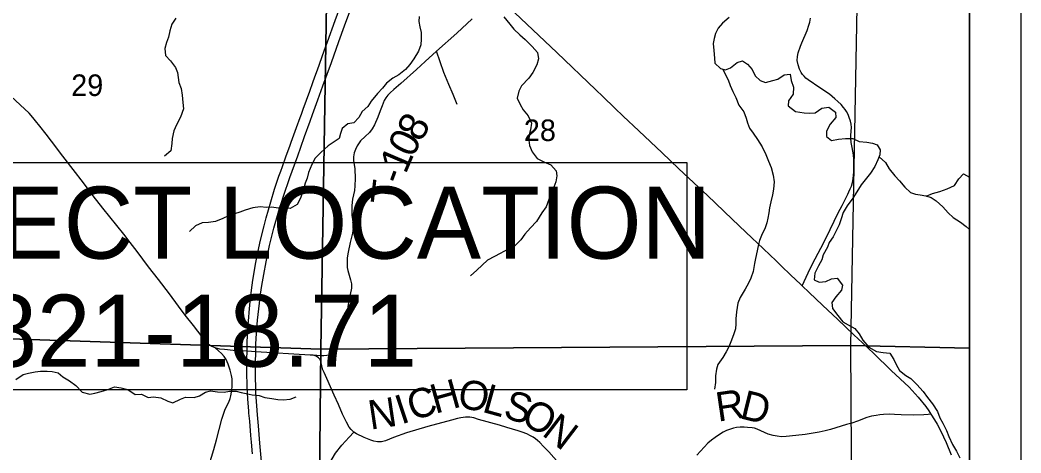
# Model space of a CAD drawing. Extents: x 0 to 34, y 0 to 22.
# Drawn here: x 28.471 to 30.417, y 15.384 to 16.225 of the extents above; entities that cross this region are included whole.
import ezdxf

# ---------------------------------------------------------------- set-up
doc = ezdxf.new("R2010")
doc.units = 0
for name, color, linetype in [('GM_X_Corporation', 7, 'Continuous'), ('GM_X_County_Road', 7, 'Continuous'), ('GM_X_County_Road_Text', 7, 'Continuous'), ('GM_X_Interstate_Route', 7, 'Continuous'), ('GM_X_Minor_River', 7, 'Continuous'), ('GM_X_Section_Text', 7, 'Continuous'), ('GM_X_State_Route', 7, 'Continuous'), ('GM_X_Township_Road', 7, 'Continuous'), ('GM_X_Township_Road_Text', 7, 'Continuous'), ('SH_Data', 7, 'Continuous'), ('SH_Masking', 7, 'Continuous'), ('SH_Text', 7, 'Continuous')]:
    doc.layers.add(name, color=color, linetype=linetype)

msp = doc.modelspace()

# ---------------------------------------------------------------- linework, layer by layer
at = {"layer": 'GM_X_Corporation'}
for points in [[(23.5167, 14.1), (30.3167, 14.1), (30.3167, 18.565), (30.101, 18.5701), (29.6772, 18.5786), (29.6561, 18.5791), (29.0074, 18.5935), (28.7772, 18.6028), (28.3421, 18.6121), (27.3971, 18.6436), (27.1064, 18.6537), (27.1039, 18.5696), (27.0944, 18.0731), (27.0775, 16.888), (27.0694, 16.6556), (27.0676, 16.5549), (27.052, 15.403), (27.043, 14.755), (27.046, 14.6155), (27.01, 14.6164), (26.6535, 14.621)], [(27.0676, 16.5549), (27.052, 15.403), (27.043, 14.755), (27.046, 14.6155), (27.2076, 14.6118), (27.2151, 14.6117), (27.2601, 14.6106), (27.262, 14.6106), (27.3217, 14.6092), (27.3244, 14.6092), (28.7538, 14.5726), (28.7592, 14.5724), (28.9743, 14.568), (28.9779, 14.5679), (28.9904, 14.5676), (29.257, 14.5621), (29.2606, 14.562), (30.0913, 14.5411), (30.0947, 14.5411), (30.3167, 14.5373), (30.3167, 18.565)]]:
    msp.add_lwpolyline(points, dxfattribs=at)
for points in [[(28.0831, 16.631), (29.0727, 16.6129), (29.0554, 15.5858), (28.0603, 15.6194)], [(29.0727, 16.6129), (30.104, 16.5971), (30.0852, 15.5935), (29.0554, 15.5858)], [(30.3167, 15.5879), (30.3167, 16.5929), (30.104, 16.5971), (30.0852, 15.5935)], [(29.0554, 15.5858), (29.0455, 14.5648), (28.107, 14.591), (28.0653, 14.5914), (28.0603, 15.6194)], [(30.0852, 15.5935), (30.0916, 14.542), (29.1115, 14.5644), (29.0455, 14.5648), (29.0554, 15.5858)], [(30.3167, 14.5377), (30.3167, 15.5879), (30.0852, 15.5935), (30.0916, 14.542)]]:
    msp.add_lwpolyline(points, close=True, dxfattribs=at)
at = {"layer": 'GM_X_County_Road'}
for points in [[(29.0586, 15.5484), (29.0574, 15.5535), (29.056, 15.5595), (29.0548, 15.5639), (29.0534, 15.5665), (29.051, 15.5691), (29.0467, 15.5722), (29.0404, 15.5742), (29.0348, 15.5747), (28.929, 15.581), (28.9122, 15.5822), (28.8854, 15.5838), (28.8681, 15.5851), (28.8594, 15.5862), (28.85, 15.5884), (28.8438, 15.5911), (28.8375, 15.5954), (28.8311, 15.6014), (28.8247, 15.6099), (28.8081, 15.6319), (28.7917, 15.6523), (28.7789, 15.6696), (28.7617, 15.6935), (28.7403, 15.7211), (28.7208, 15.7459), (28.6986, 15.7755), (28.6848, 15.7933), (28.6725, 15.8093), (28.632, 15.8603), (28.6131, 15.8842), (28.5945, 15.909), (28.5542, 15.9607), (28.5319, 15.9899), (28.5215, 16.0038), (28.5095, 16.0195), (28.5012, 16.0297), (28.496, 16.036), (28.4885, 16.0443), (28.4445, 16.0856)], [(28.8362, 15.3529), (28.8476, 15.3911), (28.8529, 15.4102), (28.8634, 15.4499), (28.8699, 15.4692), (28.8768, 15.4828), (28.8796, 15.4905), (28.8807, 15.4951), (28.8819, 15.5024), (28.8832, 15.5132), (28.8835, 15.5205), (28.8835, 15.5283), (28.8821, 15.5352), (28.8794, 15.5451), (28.8753, 15.5568), (28.8716, 15.5657), (28.8678, 15.5719), (28.8622, 15.5778), (28.8564, 15.5829), (28.85, 15.5884)], [(29.5282, 15.3538), (29.4987, 15.3865), (29.4886, 15.3972), (29.4816, 15.4049), (29.4771, 15.4089), (29.4728, 15.4121), (29.4682, 15.4154), (29.4632, 15.418), (29.456, 15.4214), (29.4472, 15.4248), (29.4391, 15.4274), (29.4174, 15.4342), (29.4028, 15.4386), (29.3619, 15.4496), (29.3529, 15.4524), (29.3453, 15.4538), (29.3367, 15.4541), (29.328, 15.4528), (29.3214, 15.4514), (29.3094, 15.4484), (29.2637, 15.4356), (29.2219, 15.4234), (29.1969, 15.4142), (29.1812, 15.4079), (29.1736, 15.4059), (29.1659, 15.4058), (29.1585, 15.4074), (29.1527, 15.4092), (29.1398, 15.4146), (29.125, 15.4213), (29.1195, 15.425), (29.1145, 15.4297), (29.1107, 15.4348), (29.1056, 15.4442), (29.098, 15.4601), (29.0902, 15.4783), (29.0817, 15.4969), (29.0674, 15.529), (29.0619, 15.541), (29.0588, 15.5473), (29.0586, 15.5484)], [(30.2417, 15.4597), (30.2362, 15.4589), (30.228, 15.4585), (30.2084, 15.4581), (30.184, 15.4588), (30.171, 15.4591), (30.161, 15.4595), (30.1497, 15.4593), (30.1422, 15.4585), (30.1349, 15.4574), (30.1259, 15.4556), (30.1173, 15.4531), (30.0987, 15.4463), (30.0877, 15.4426), (30.0772, 15.4397), (30.0464, 15.4303), (30.0357, 15.4276), (30.0242, 15.4249), (29.9971, 15.4202), (29.9912, 15.4195), (29.9599, 15.4161), (29.9508, 15.416), (29.9429, 15.4169), (29.9349, 15.4184), (29.9255, 15.4212), (29.9037, 15.4307), (29.8987, 15.4323), (29.8938, 15.4331), (29.8853, 15.4341), (29.8783, 15.4344), (29.8706, 15.4343), (29.8636, 15.4337), (29.8579, 15.4325), (29.8503, 15.4302), (29.8444, 15.4279), (29.8375, 15.4247), (29.8304, 15.4204), (29.8219, 15.4146), (29.815, 15.4094), (29.8077, 15.4032), (29.7862, 15.3803)]]:
    msp.add_lwpolyline(points, dxfattribs=at)
at = {"layer": 'GM_X_Interstate_Route'}
for points in [[(28.9229, 15.3828), (28.921, 15.4055), (28.9197, 15.4182), (28.9173, 15.4465), (28.9159, 15.4616), (28.9155, 15.4664), (28.9139, 15.4887), (28.9125, 15.5152), (28.9117, 15.5401), (28.9117, 15.56), (28.9118, 15.5674), (28.9122, 15.5822), (28.9124, 15.5998), (28.9131, 15.612), (28.9138, 15.6267), (28.9153, 15.648), (28.9162, 15.6572), (28.9191, 15.6855), (28.9236, 15.72), (28.9295, 15.7547), (28.9333, 15.7736), (28.9384, 15.7981), (28.9451, 15.8255), (28.949, 15.841), (28.9581, 15.8722), (28.9655, 15.8969), (28.9741, 15.9224), (28.9776, 15.9319), (28.9808, 15.9411), (28.9883, 15.9619), (28.9951, 15.9805), (28.9976, 15.9881), (29.0082, 16.0169), (29.0153, 16.036), (29.0177, 16.0426), (29.021, 16.0522), (29.034, 16.0873), (29.0402, 16.1044), (29.044, 16.1151), (29.0489, 16.1286), (29.0621, 16.1659), (29.0684, 16.1829), (29.0835, 16.2246), (29.0946, 16.2545)], [(28.9414, 15.3536), (28.9371, 15.4037), (28.9341, 15.4369), (28.9324, 15.4585), (28.9293, 15.5021), (28.9292, 15.5108), (28.9285, 15.5325), (28.9285, 15.5596), (28.929, 15.581), (28.9295, 15.5962), (28.9305, 15.6163), (28.9326, 15.6424), (28.9361, 15.6752), (28.9383, 15.6931), (28.9408, 15.71), (28.9445, 15.7308), (28.9491, 15.7557), (28.9561, 15.7875), (28.9597, 15.8032), (28.9642, 15.8209), (28.9739, 15.8551), (28.9828, 15.8832), (28.9952, 15.9196), (29.0107, 15.9619), (29.0169, 15.9787), (29.024, 15.9989), (29.0351, 16.0292), (29.0395, 16.0421), (29.0497, 16.0705), (29.0596, 16.0974), (29.0763, 16.1429), (29.0907, 16.184), (29.1019, 16.2142), (29.1175, 16.2573)]]:
    msp.add_lwpolyline(points, dxfattribs=at)
at = {"layer": 'GM_X_Minor_River'}
for points in [[(28.7736, 16.2294), (28.7657, 16.2177), (28.7623, 16.2044), (28.7594, 16.1919), (28.7556, 16.182), (28.7522, 16.1702), (28.7534, 16.1566), (28.7633, 16.1464), (28.7728, 16.1332), (28.777, 16.1233), (28.7793, 16.1044), (28.7839, 16.0926), (28.7862, 16.0794), (28.787, 16.065), (28.7885, 16.0529), (28.7829, 16.0369), (28.775, 16.0217), (28.7697, 16.01), (28.7667, 15.9955), (28.766, 15.9857), (28.7638, 15.9713), (28.7517, 15.961)], [(29.2465, 16.2322), (29.2462, 16.2224), (29.2481, 16.2125), (29.2504, 16.2015), (29.2508, 16.1886), (29.2497, 16.1776), (29.2452, 16.1647), (29.2362, 16.1503), (29.2283, 16.1389), (29.2199, 16.1294), (29.2071, 16.1191), (29.1958, 16.1123), (29.1833, 16.1027), (29.1754, 16.0932), (29.1659, 16.083), (29.1535, 16.0681), (29.1467, 16.0575), (29.1361, 16.0476), (29.1294, 16.0358), (29.1195, 16.026), (29.1078, 16.024), (29.0972, 16.0145), (29.0939, 16.005), (29.0909, 15.9951), (29.0795, 15.9875), (29.0697, 15.981), (29.0553, 15.9681), (29.0448, 15.9571), (29.038, 15.9445), (29.0316, 15.929), (29.029, 15.9184), (29.0252, 15.9085), (29.0215, 15.8945), (29.0162, 15.8793), (29.0094, 15.8671), (28.9958, 15.8595), (28.9826, 15.8602), (28.9727, 15.8602), (28.9606, 15.862), (28.95, 15.8612), (28.9379, 15.8623), (28.9235, 15.8604), (28.9088, 15.8558), (28.8978, 15.8523), (28.888, 15.8489), (28.8759, 15.8454), (28.8653, 15.8401), (28.8505, 15.8343), (28.8373, 15.832), (28.8252, 15.8312), (28.8119, 15.8255), (28.8002, 15.8145)], [(29.4112, 16.2316), (29.423, 16.2177), (29.431, 16.2078), (29.4424, 16.1965), (29.4526, 16.1878), (29.4663, 16.1738), (29.4766, 16.1621), (29.4789, 16.15), (29.4755, 16.1382), (29.4676, 16.1234), (29.4601, 16.1128), (29.4457, 16.0976), (29.4404, 16.0873), (29.4371, 16.0737), (29.4428, 16.0616), (29.4489, 16.0513), (29.4584, 16.0392), (29.4649, 16.0252), (29.463, 16.0123), (29.4608, 16.0025), (29.46, 15.9922), (29.4612, 15.9816), (29.4665, 15.9691), (29.4764, 15.9563), (29.4893, 15.9499), (29.5026, 15.9439), (29.5132, 15.9325), (29.5144, 15.9231), (29.5125, 15.9113), (29.5088, 15.9007), (29.5027, 15.8878), (29.499, 15.8771), (29.4934, 15.8623), (29.4854, 15.8506), (29.4749, 15.8342), (29.4632, 15.8221), (29.4522, 15.8095), (29.4443, 15.7985), (29.4322, 15.7859), (29.4186, 15.7798), (29.4043, 15.7718), (29.3929, 15.7661), (29.3797, 15.7592), (29.3691, 15.749), (29.3589, 15.7398), (29.3465, 15.7288)], [(29.8493, 16.2301), (29.8365, 16.2191), (29.8278, 16.2096), (29.8229, 16.1993), (29.8199, 16.1898), (29.818, 16.18), (29.8196, 16.166), (29.8208, 16.1516), (29.8216, 16.1417), (29.8326, 16.1315), (29.842, 16.1289), (29.8519, 16.1327), (29.8647, 16.143), (29.8753, 16.1461), (29.8852, 16.14), (29.8939, 16.1291), (29.8996, 16.1173), (29.9095, 16.1083), (29.9201, 16.1041), (29.9341, 16.1083), (29.944, 16.1103), (29.9564, 16.119), (29.9678, 16.1206), (29.9701, 16.1081), (29.9747, 16.0948), (29.9736, 16.0816), (29.9649, 16.0687), (29.9642, 16.0588), (29.9786, 16.0479), (29.9949, 16.0449), (30.0055, 16.0445), (30.0165, 16.0453), (30.0293, 16.0545), (30.0433, 16.0564), (30.0558, 16.0466), (30.0566, 16.0364), (30.0457, 16.0231), (30.0385, 16.0098), (30.0389, 15.9992), (30.0484, 15.9916), (30.0621, 15.9943), (30.0753, 15.9955)], [(29.8363, 16.1305), (29.8474, 16.1096), (29.8516, 16.0986), (29.8566, 16.0865), (29.8623, 16.0747), (29.868, 16.06), (29.8779, 16.0471), (29.8825, 16.035), (29.8848, 16.0255), (29.8886, 16.0153), (29.8958, 16.0055), (29.9042, 15.9934), (29.9133, 15.9794), (29.9205, 15.9643), (29.9259, 15.9514), (29.9312, 15.9393), (29.9347, 15.9241), (29.9366, 15.9112), (29.9355, 15.8972), (29.9336, 15.8858), (29.9306, 15.8722), (29.9277, 15.8604), (29.9265, 15.8509), (29.9247, 15.8407), (29.9224, 15.8312), (29.9187, 15.8198), (29.9134, 15.81), (29.9085, 15.7974), (29.9055, 15.7868), (29.9037, 15.7773), (29.9003, 15.7622), (29.8984, 15.7527), (29.8958, 15.7371), (29.8917, 15.7242), (29.8872, 15.7143), (29.8804, 15.7026), (29.8706, 15.6862), (29.8665, 15.6756), (29.8635, 15.6589), (29.8624, 15.6453), (29.8624, 15.6354), (29.8617, 15.6256), (29.8587, 15.6161), (29.8538, 15.6035), (29.8489, 15.5906), (29.8433, 15.5808), (29.8373, 15.5698), (29.8275, 15.5565), (29.8245, 15.547), (29.823, 15.5341), (29.8226, 15.5216), (29.8208, 15.5083)], [(30.0753, 15.9955), (30.0897, 15.9952), (30.1022, 15.9895), (30.117, 15.9884), (30.128, 15.9862), (30.1374, 15.9832), (30.1428, 15.973), (30.1424, 15.9635), (30.1387, 15.954), (30.1323, 15.9411), (30.124, 15.9278), (30.1164, 15.9183), (30.1062, 15.905), (30.0976, 15.8917), (30.09, 15.8796), (30.0787, 15.8647), (30.0708, 15.8514), (30.0674, 15.8393), (30.0633, 15.8279), (30.0573, 15.8158), (30.0513, 15.804), (30.0441, 15.7933), (30.0403, 15.7839), (30.0324, 15.7694), (30.0294, 15.7599), (30.023, 15.7478), (30.0159, 15.7337), (30.0148, 15.7208), (30.0243, 15.716), (30.0371, 15.7175), (30.0485, 15.7225), (30.0594, 15.7237), (30.0697, 15.7104), (30.0678, 15.7006), (30.0565, 15.688), (30.049, 15.6766), (30.0505, 15.6652), (30.0608, 15.6513), (30.0703, 15.6392), (30.0809, 15.6331), (30.0934, 15.6264), (30.1018, 15.6161), (30.109, 15.6037), (30.1208, 15.5901), (30.1356, 15.5814), (30.1488, 15.5795), (30.1617, 15.5781), (30.1697, 15.566), (30.1739, 15.5561), (30.1804, 15.5448), (30.1925, 15.5346), (30.2028, 15.5289), (30.2145, 15.5176), (30.2263, 15.5036), (30.2351, 15.4919), (30.2449, 15.4798), (30.2544, 15.465), (30.259, 15.4526), (30.2647, 15.4423), (30.2716, 15.428), (30.2766, 15.4162), (30.2838, 15.4011), (30.291, 15.3882), (30.2975, 15.375)], [(30.1409, 15.9598), (30.1531, 15.9484), (30.1607, 15.9363), (30.1717, 15.923), (30.1804, 15.9132), (30.1907, 15.9011), (30.2017, 15.8905), (30.2116, 15.8875), (30.221, 15.8857), (30.2316, 15.8838), (30.2419, 15.8804), (30.2521, 15.874), (30.2646, 15.8627), (30.2753, 15.8506), (30.2851, 15.8416), (30.2988, 15.8325), (30.3098, 15.8246), (30.3167, 15.8188)], [(30.2325, 15.8835), (30.2449, 15.8888), (30.2592, 15.8923), (30.2732, 15.8976), (30.2876, 15.9037), (30.2959, 15.917), (30.3046, 15.9265), (30.3167, 15.9205)], [(28.4626, 15.5271), (28.4769, 15.537), (28.4875, 15.5397), (28.5, 15.542), (28.5106, 15.5435), (28.5235, 15.5432), (28.5333, 15.5425), (28.5447, 15.5399), (28.5542, 15.5323), (28.5667, 15.5244), (28.5796, 15.5157), (28.5914, 15.5025), (28.6062, 15.4984), (28.6164, 15.5003), (28.6285, 15.5038), (28.6417, 15.508), (28.6546, 15.5126), (28.6675, 15.5111), (28.6807, 15.5077), (28.6944, 15.4979), (28.7069, 15.4984), (28.7201, 15.4923), (28.7304, 15.4935), (28.7448, 15.4913), (28.7584, 15.4849), (28.7679, 15.4819), (28.783, 15.4892), (28.7928, 15.493), (28.8095, 15.4919), (28.8197, 15.4954), (28.8311, 15.5026), (28.8413, 15.5049), (28.8549, 15.5031), (28.8674, 15.5027), (28.878, 15.5043), (28.8913, 15.5043), (28.9007, 15.5017), (28.9106, 15.5002), (28.9223, 15.4972), (28.936, 15.4958), (28.9469, 15.4924), (28.9606, 15.4902), (28.9723, 15.4883), (28.9826, 15.4876), (28.9958, 15.4891), (29.0075, 15.4934)]]:
    msp.add_lwpolyline(points, dxfattribs=at)
at = {"layer": 'GM_X_State_Route'}
msp.add_lwpolyline([(29.3976, 16.2731), (29.5141, 16.1623), (29.5901, 16.09), (29.6039, 16.0766), (29.627, 16.0543), (29.6432, 16.039), (29.6738, 16.0101), (29.7194, 15.9674), (29.7511, 15.9372), (29.7905, 15.9001), (29.8065, 15.885), (29.8233, 15.8693), (29.855, 15.8388), (29.8817, 15.8134), (29.9158, 15.781), (29.9405, 15.7575), (29.9504, 15.7482), (29.9694, 15.7301), (29.9878, 15.7125), (29.9915, 15.7091), (30.0048, 15.6964), (30.0308, 15.6717), (30.0607, 15.6434), (30.0915, 15.6139), (30.1089, 15.5981), (30.1306, 15.5774), (30.1643, 15.5449), (30.1995, 15.512), (30.217, 15.4931), (30.2318, 15.4746), (30.2376, 15.4663), (30.2417, 15.4597), (30.2487, 15.4489), (30.2538, 15.4404), (30.2596, 15.4292), (30.2663, 15.416), (30.2714, 15.4045), (30.2807, 15.3807)], dxfattribs=at)
at = {"layer": 'GM_X_Township_Road'}
for points in [[(29.9915, 15.7091), (30.0028, 15.7343), (30.0116, 15.7519), (30.0274, 15.7826), (30.0383, 15.8039), (30.0455, 15.8183), (30.0615, 15.8508), (30.0688, 15.865), (30.0801, 15.8875), (30.0822, 15.8918), (30.0847, 15.8973), (30.087, 15.9026), (30.0889, 15.9096), (30.0905, 15.9168), (30.0919, 15.9308), (30.0919, 15.9454), (30.0917, 15.9546), (30.0909, 15.9634), (30.0882, 15.9779), (30.0863, 15.9877), (30.0856, 15.9958), (30.0861, 16.0021), (30.0871, 16.0166), (30.0867, 16.0233), (30.0854, 16.0289), (30.0829, 16.0361), (30.0804, 16.0422), (30.0774, 16.0475), (30.0751, 16.0515), (30.0719, 16.0558), (30.0671, 16.0616), (30.0609, 16.0674), (30.0551, 16.0727), (30.0446, 16.0814), (30.0259, 16.0937), (30.0029, 16.1091), (29.9986, 16.1127), (29.9953, 16.1162), (29.9919, 16.1199), (29.9894, 16.1237), (29.9864, 16.1297), (29.9836, 16.1384), (29.9818, 16.147), (29.9822, 16.1544), (29.9835, 16.162), (29.9882, 16.1747), (29.9906, 16.1812), (30.0008, 16.2054), (30.0043, 16.2154), (30.0059, 16.2211), (30.0076, 16.2293)], [(29.35, 16.2277), (29.3199, 16.1999), (29.2805, 16.1649), (29.2583, 16.1452), (29.2415, 16.1294), (29.2108, 16.1021), (29.1976, 16.0906), (29.1904, 16.084), (29.1859, 16.0793), (29.182, 16.0741), (29.179, 16.069), (29.175, 16.059), (29.1708, 16.0488), (29.1661, 16.0365), (29.1598, 16.0221), (29.1555, 16.0142), (29.1501, 16.0068), (29.1415, 15.999), (29.1327, 15.9907), (29.1288, 15.9852), (29.1263, 15.9808), (29.1227, 15.9737), (29.1203, 15.9673), (29.1191, 15.9599), (29.1194, 15.9529), (29.1215, 15.9364), (29.1224, 15.9175), (29.1218, 15.9036), (29.1208, 15.894), (29.1174, 15.8777), (29.1158, 15.8653), (29.1156, 15.8557), (29.1161, 15.8467), (29.1179, 15.8332), (29.1182, 15.8277), (29.1183, 15.8215), (29.118, 15.8166), (29.1171, 15.8112), (29.1128, 15.7931), (29.1087, 15.7744), (29.1069, 15.7636), (29.1065, 15.7575), (29.1065, 15.7522), (29.107, 15.7449), (29.1083, 15.7386), (29.1135, 15.7209), (29.1149, 15.7131), (29.115, 15.7048), (29.1096, 15.6766), (29.1065, 15.66), (29.1044, 15.6466), (29.1028, 15.6387), (29.0958, 15.6184), (29.0918, 15.6065), (29.0899, 15.5995), (29.0882, 15.592), (29.0872, 15.586), (29.0845, 15.5811), (29.0807, 15.5775), (29.0777, 15.5759), (29.0731, 15.5746), (29.0675, 15.5735), (29.0616, 15.5728), (29.0542, 15.5729), (29.0475, 15.5735), (29.0404, 15.5742)], [(29.3208, 16.0611), (29.313, 16.0807), (29.3041, 16.1004), (29.2947, 16.1237), (29.2805, 16.1649)], [(29.0544, 15.1854), (29.0553, 15.2283), (29.0562, 15.2707), (29.0582, 15.3082), (29.0595, 15.3227), (29.0608, 15.3314), (29.0626, 15.3404), (29.0682, 15.3566), (29.0717, 15.3633), (29.0775, 15.3733), (29.0839, 15.3838), (29.0962, 15.3993), (29.1109, 15.4152), (29.1195, 15.425)]]:
    msp.add_lwpolyline(points, dxfattribs=at)
at = {"layer": 'SH_Data'}
for points in [[(23.4167, 21), (30.4167, 21), (30.4167, 14), (23.4167, 14)], [(23.5167, 20.9), (30.3167, 20.9), (30.3167, 14.1), (23.5167, 14.1)]]:
    msp.add_lwpolyline(points, close=True, dxfattribs=at)
at = {"layer": 'SH_Masking'}
msp.add_lwpolyline([(27.8981, 15.9486), (29.7674, 15.9486), (29.7674, 15.5072), (27.8981, 15.5072)], close=True, dxfattribs=at)
at = {"layer": 'SH_Text'}
msp.add_lwpolyline([(27.8981, 15.9486), (29.7674, 15.9486), (29.7674, 15.5072), (27.8981, 15.5072)], close=True, dxfattribs=at)

# ---------------------------------------------------------------- texts
at = {"layer": 'GM_X_County_Road_Text'}
for s, rotation, p in [('C', 17.0933, (29.2336, 15.4466)), ('H', 15.5481, (29.2779, 15.4602)), ('O', 349.8639, (29.3194, 15.4733)), ('L', 344.5167, (29.3672, 15.4648)), ('N', 8.4598, (29.152, 15.4295)), ('I', 18.3232, (29.2118, 15.4394)), ('S', 343.7864, (29.408, 15.4535)), ('R', 8.3465, (29.8276, 15.4451)), ('D', 346.1617, (29.868, 15.4522)), ('O', 329.9971, (29.4415, 15.4442)), ('N', 322.572, (29.4832, 15.4203))]:
    msp.add_text(s, height=0.0568, rotation=rotation, dxfattribs=at).set_placement(p)
at = {"layer": 'GM_X_Section_Text'}
for s, p in [('29', (28.5703, 16.0779)), ('28', (29.4503, 15.9904))]:
    msp.add_text(s, height=0.04186, rotation=0, dxfattribs=at).set_placement(p)
at = {"layer": 'GM_X_Township_Road_Text'}
for s, rotation, p in [('8', 60.3055, (29.2496, 15.9864)), ('0', 62.4993, (29.2337, 15.9559)), ('1', 66.9606, (29.2205, 15.9247)), ('-', 69.8468, (29.2127, 15.9035)), ('T', 83.5926, (29.2088, 15.8648))]:
    msp.add_text(s, height=0.0568, rotation=rotation, dxfattribs=at).set_placement(p)
at = {"layer": 'SH_Text'}
for s, p in [('PROJECT LOCATION', (27.9315, 15.7619)), ('NOB-821-18.71', (27.9315, 15.5519))]:
    msp.add_text(s, height=0.14, dxfattribs=at).set_placement(p)

doc.saveas('drawing.dxf')
